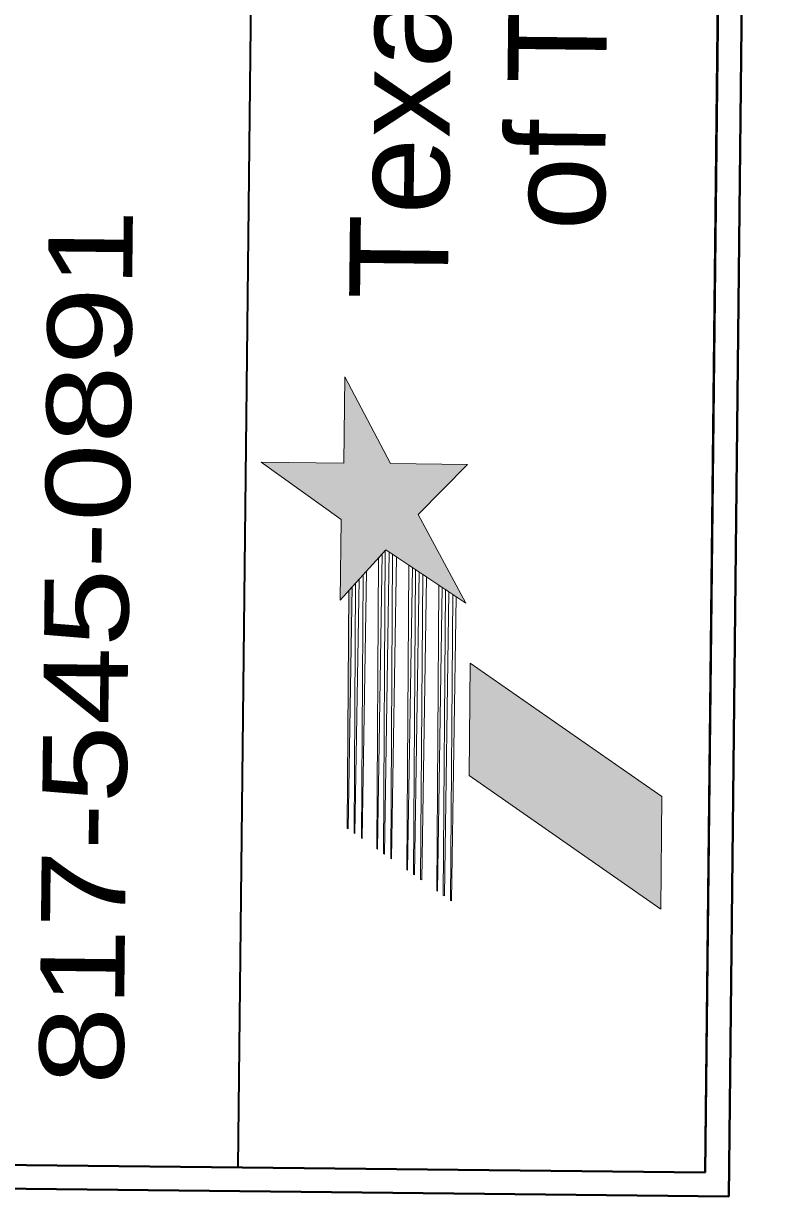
# Model space of a CAD drawing. Extents: x 2356576 to 2377878, y 6966390 to 6990634.
# Drawn here: x 2366780.1 to 2366937.2, y 6968641.2 to 6968887 of the extents above; entities that cross this region are included whole.
import ezdxf
from ezdxf.enums import TextEntityAlignment as Align

# ---------------------------------------------------------------- set-up
doc = ezdxf.new("R2010")
doc.units = 0
doc.header["$LTSCALE"] = 7.1
doc.layers.add('19', color=7, linetype='Continuous', lineweight=13)
doc.layers.add('8', color=7, linetype='Continuous', lineweight=13)

msp = doc.modelspace()

# ---------------------------------------------------------------- hatches: boundary and pattern name
at = {"layer": '19'}
for points in [[(2366829.855, 6968795.042), (2366846.615, 6968783.06), (2366846.429, 6968766.154), (2366855.975, 6968776.676), (2366872.765, 6968765.486), (2366862.737, 6968784.052), (2366873.089, 6968794.562), (2366856.961, 6968794.74), (2366847.355, 6968812.93), (2366847.159, 6968794.85)], [(2366847.897, 6968718.334), (2366848.233, 6968768.122), (2366848.919, 6968768.914), (2366848.107, 6968718.222)], [(2366873.411, 6968729.38), (2366913.565, 6968701.404), (2366913.827, 6968724.988), (2366873.667, 6968752.948)]]:
    msp.add_hatch(color=256, dxfattribs=at).paths.add_polyline_path(points)
at = {"layer": '8'}
for points in [[(2366829.855, 6968795.042), (2366846.615, 6968783.06), (2366846.429, 6968766.154), (2366855.975, 6968776.676), (2366872.765, 6968765.486), (2366862.737, 6968784.052), (2366873.089, 6968794.562), (2366856.961, 6968794.74), (2366847.355, 6968812.93), (2366847.159, 6968794.85)], [(2366847.897, 6968718.334), (2366848.233, 6968768.122), (2366848.919, 6968768.914), (2366848.107, 6968718.222)], [(2366873.411, 6968729.38), (2366913.565, 6968701.404), (2366913.827, 6968724.988), (2366873.667, 6968752.948)]]:
    msp.add_hatch(color=256, dxfattribs=at).paths.add_polyline_path(points)

# ---------------------------------------------------------------- linework, layer by layer
at = {"layer": '19', "lineweight": 35}
for p, q in [((2366931.855, 6969453.45), (2366922.891, 6968646.236)), ((2366830.221, 6969120.006), (2366824.971, 6968647.324)), ((2366217.375, 6968654.072), (2366922.891, 6968646.236))]:
    msp.add_line(p, q, dxfattribs=at)
at = {"layer": '19', "lineweight": 40}
msp.add_lwpolyline([(2363758.773, 6990629.355), (2367158.576, 6990592.767), (2366922.891, 6968646.236), (2363523.088, 6968682.826)], close=True, dxfattribs=at)
at = {"layer": '19'}
for points in [[(2366829.855, 6968795.042), (2366846.615, 6968783.06), (2366846.429, 6968766.154), (2366855.975, 6968776.676), (2366872.765, 6968765.486), (2366862.737, 6968784.052), (2366873.089, 6968794.562), (2366856.961, 6968794.74), (2366847.355, 6968812.93), (2366847.159, 6968794.85)], [(2366854.059, 6968714.05), (2366854.421, 6968774.956), (2366855.237, 6968775.832), (2366854.261, 6968713.93)], [(2366855.461, 6968713.052), (2366855.837, 6968776.486), (2366855.975, 6968776.662), (2366856.681, 6968776.188), (2366855.679, 6968712.942)], [(2366856.993, 6968712.012), (2366857.399, 6968775.732), (2366858.219, 6968775.178), (2366857.193, 6968711.92)], [(2366860.351, 6968709.66), (2366860.779, 6968773.48), (2366861.567, 6968772.952), (2366860.537, 6968709.54)], [(2366849.319, 6968717.346), (2366849.651, 6968769.698), (2366850.377, 6968770.484), (2366849.497, 6968717.21)], [(2366850.845, 6968716.278), (2366851.219, 6968771.422), (2366851.927, 6968772.196), (2366851.039, 6968716.186)], [(2366861.751, 6968708.656), (2366862.187, 6968772.526), (2366862.959, 6968772.016), (2366861.947, 6968708.564)], [(2366863.267, 6968707.622), (2366863.703, 6968771.514), (2366864.483, 6968770.988), (2366863.481, 6968707.504)], [(2366847.897, 6968718.334), (2366848.233, 6968768.122), (2366848.919, 6968768.914), (2366848.107, 6968718.222)], [(2366866.635, 6968705.27), (2366867.057, 6968769.282), (2366867.801, 6968768.78), (2366866.831, 6968705.15)], [(2366868.015, 6968704.272), (2366868.467, 6968768.35), (2366869.201, 6968767.85), (2366868.229, 6968704.16)], [(2366869.555, 6968703.238), (2366869.979, 6968767.33), (2366870.727, 6968766.816), (2366869.731, 6968703.108)], [(2366873.411, 6968729.38), (2366913.565, 6968701.404), (2366913.827, 6968724.988), (2366873.667, 6968752.948)]]:
    msp.add_lwpolyline(points, close=True, dxfattribs=at)
at = {"layer": '8', "lineweight": 35}
for p, q in [((2366931.855, 6969453.45), (2366922.891, 6968646.236)), ((2366830.221, 6969120.006), (2366824.971, 6968647.324)), ((2366217.375, 6968654.072), (2366922.891, 6968646.236))]:
    msp.add_line(p, q, dxfattribs=at)
at = {"layer": '8', "lineweight": 40}
for points in [[(2363753.827, 6990634.409), (2367163.63, 6990597.713), (2366927.837, 6968641.182), (2363518.034, 6968677.88)], [(2363758.773, 6990629.355), (2367158.576, 6990592.767), (2366922.891, 6968646.236), (2363523.088, 6968682.826)]]:
    msp.add_lwpolyline(points, close=True, dxfattribs=at)
at = {"layer": '8'}
for points in [[(2366829.855, 6968795.042), (2366846.615, 6968783.06), (2366846.429, 6968766.154), (2366855.975, 6968776.676), (2366872.765, 6968765.486), (2366862.737, 6968784.052), (2366873.089, 6968794.562), (2366856.961, 6968794.74), (2366847.355, 6968812.93), (2366847.159, 6968794.85)], [(2366854.059, 6968714.05), (2366854.421, 6968774.956), (2366855.237, 6968775.832), (2366854.261, 6968713.93)], [(2366855.461, 6968713.052), (2366855.837, 6968776.486), (2366855.975, 6968776.662), (2366856.681, 6968776.188), (2366855.679, 6968712.942)], [(2366856.993, 6968712.012), (2366857.399, 6968775.732), (2366858.219, 6968775.178), (2366857.193, 6968711.92)], [(2366860.351, 6968709.66), (2366860.779, 6968773.48), (2366861.567, 6968772.952), (2366860.537, 6968709.54)], [(2366849.319, 6968717.346), (2366849.651, 6968769.698), (2366850.377, 6968770.484), (2366849.497, 6968717.21)], [(2366850.845, 6968716.278), (2366851.219, 6968771.422), (2366851.927, 6968772.196), (2366851.039, 6968716.186)], [(2366861.751, 6968708.656), (2366862.187, 6968772.526), (2366862.959, 6968772.016), (2366861.947, 6968708.564)], [(2366863.267, 6968707.622), (2366863.703, 6968771.514), (2366864.483, 6968770.988), (2366863.481, 6968707.504)], [(2366847.897, 6968718.334), (2366848.233, 6968768.122), (2366848.919, 6968768.914), (2366848.107, 6968718.222)], [(2366866.635, 6968705.27), (2366867.057, 6968769.282), (2366867.801, 6968768.78), (2366866.831, 6968705.15)], [(2366868.015, 6968704.272), (2366868.467, 6968768.35), (2366869.201, 6968767.85), (2366868.229, 6968704.16)], [(2366869.555, 6968703.238), (2366869.979, 6968767.33), (2366870.727, 6968766.816), (2366869.731, 6968703.108)], [(2366873.411, 6968729.38), (2366913.565, 6968701.404), (2366913.827, 6968724.988), (2366873.667, 6968752.948)]]:
    msp.add_lwpolyline(points, close=True, dxfattribs=at)

# ---------------------------------------------------------------- texts
at = {"layer": '19', "width": 1.05}
msp.add_text('Texas Department', height=20.67, rotation=89.364, dxfattribs=at).set_placement((2366870.269, 6968948.427), align=Align.CENTER)
at = {"layer": '19'}
msp.add_text('of Transportation', height=20.67, rotation=89.364, dxfattribs=at).set_placement((2366902.939, 6968947.987), align=Align.CENTER)
at = {"layer": '19', "width": 1.25}
msp.add_text('817-545-0891', height=17.63, rotation=89.364, dxfattribs=at).set_placement((2366800.967, 6968664.488))
at = {"layer": '8', "width": 1.05}
msp.add_text('Texas Department', height=20.67, rotation=89.364, dxfattribs=at).set_placement((2366870.269, 6968948.427), align=Align.CENTER)
at = {"layer": '8'}
msp.add_text('of Transportation', height=20.67, rotation=89.364, dxfattribs=at).set_placement((2366902.939, 6968947.987), align=Align.CENTER)
at = {"layer": '8', "width": 1.25}
msp.add_text('817-545-0891', height=17.63, rotation=89.364, dxfattribs=at).set_placement((2366800.967, 6968664.488))

doc.saveas('drawing.dxf')
